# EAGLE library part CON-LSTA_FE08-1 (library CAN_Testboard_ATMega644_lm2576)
FEMALE HEADER
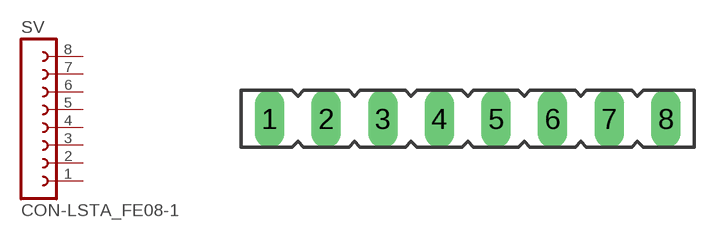
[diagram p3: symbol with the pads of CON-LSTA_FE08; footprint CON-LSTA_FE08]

Designator prefix SV

## CON-LSTA_FE08-1  [CON-LSTA_FE08]
1  1  pas
2  2  pas
3  3  pas
4  4  pas
5  5  pas
6  6  pas
7  7  pas
8  8  pas

## Footprint CON-LSTA_FE08 (pad centres in mm)
FEMALE HEADER
drill 0.813 long: 1 -8.89,0; 2 -6.35,0; 3 -3.81,0; 4 -1.27,0; 5 1.27,0; 6 3.81,0; 7 6.35,0; 8 8.89,0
